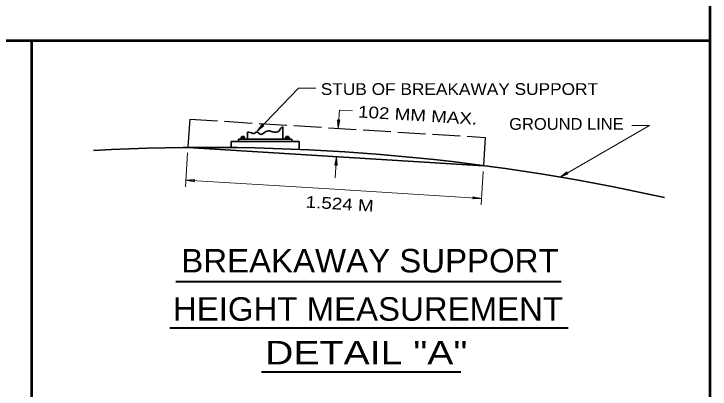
# Model space of a CAD drawing. Extents: x 312583 to 312854, y 144419 to 144597.
# Drawn here: x 312751.27 to 312796.35, y 144487.71 to 144511.98 of the extents above; entities that cross this region are included whole.
import ezdxf
from ezdxf.enums import TextEntityAlignment as Align

# ---------------------------------------------------------------- set-up
doc = ezdxf.new("R2010")
doc.units = 0
doc.header["$LTSCALE"] = 0.3
doc.linetypes.add('LONG_DASHED', pattern=[7.5, 6, -1.5])
doc.layers.add('1', color=7, linetype='Continuous', lineweight=13)

msp = doc.modelspace()

# ---------------------------------------------------------------- linework, layer by layer
at = {"layer": '1', "lineweight": 53}
for p, q in [((312796.3473, 144432.4767), (312796.3473, 144512.4926)), ((312796.3473, 144510.2401), (312717.1857, 144510.2401)), ((312752.4335, 144432.4767), (312752.4335, 144510.2401))]:
    msp.add_line(p, q, dxfattribs=at)
at = {"layer": '1'}
for p, q in [((312769.6944, 144507.1754), (312767.0264, 144504.4001)), ((312769.6944, 144507.1754), (312770.8137, 144507.1754)), ((312772.3471, 144505.7571), (312772.2781, 144504.5841)), ((312772.3471, 144505.7571), (312773.2057, 144505.7111)), ((312792.4153, 144504.7563), (312786.6377, 144501.4254)), ((312791.29, 144504.7563), (312792.4153, 144504.7563)), ((312762.3804, 144500.8044), (312762.5184, 144502.9894)), ((312772.0787, 144501.3871), (312772.1631, 144502.7364)), ((312781.5164, 144499.6238), (312781.6467, 144501.7858)), ((312762.4111, 144501.2338), (312771.6801, 144500.6588)), ((312781.5394, 144500.0531), (312771.6801, 144500.6588))]:
    msp.add_line(p, q, dxfattribs=at)
at = {"layer": '1', "linetype": 'LONG_DASHED', "lineweight": 25}
for p, q in [((312762.6564, 144505.1744), (312762.5414, 144503.3421)), ((312762.6564, 144505.1744), (312781.7847, 144503.9938)), ((312781.7847, 144503.9938), (312781.6697, 144502.1768))]:
    msp.add_line(p, q, dxfattribs=at)
at = {"layer": '1', "lineweight": 35}
for p, q in [((312768.6901, 144503.8864), (312768.6901, 144504.6761)), ((312766.3901, 144503.8864), (312766.3901, 144504.3311)), ((312765.3321, 144503.7254), (312765.3321, 144503.3804)), ((312765.8151, 144503.8864), (312765.8151, 144503.7254)), ((312765.8151, 144503.8864), (312769.2651, 144503.8864)), ((312765.9914, 144504.0091), (312765.9914, 144503.8864)), ((312766.0144, 144504.0244), (312766.1831, 144504.0244)), ((312766.0297, 144504.0628), (312766.0297, 144504.0244)), ((312766.0297, 144504.0628), (312766.1754, 144504.0628)), ((312766.0451, 144504.0091), (312766.0451, 144503.8864)), ((312766.1601, 144504.0091), (312766.1601, 144503.8864)), ((312766.1754, 144504.0628), (312766.1754, 144504.0244)), ((312766.2137, 144504.0091), (312766.2137, 144503.8864)), ((312768.8664, 144504.0091), (312768.8664, 144503.8864)), ((312768.8894, 144504.0244), (312769.0581, 144504.0244)), ((312768.9047, 144504.0628), (312768.9047, 144504.0244)), ((312768.9047, 144504.0628), (312769.0504, 144504.0628)), ((312768.9201, 144504.0091), (312768.9201, 144503.8864)), ((312769.0351, 144504.0091), (312769.0351, 144503.8864)), ((312769.0504, 144504.0628), (312769.0504, 144504.0244)), ((312769.0887, 144504.0091), (312769.0887, 144503.8864)), ((312769.2651, 144503.8864), (312769.2651, 144503.7254)), ((312762.5414, 144503.3344), (312781.6697, 144502.1538))]:
    msp.add_line(p, q, dxfattribs=at)
at = {"layer": '1', "lineweight": 40}
for p, q in [((312761.7556, 144494.6753), (312786.709, 144494.6753)), ((312761.3737, 144491.681), (312787.1546, 144491.681)), ((312767.2961, 144488.8355), (312780.2184, 144488.8355))]:
    msp.add_line(p, q, dxfattribs=at)
at = {"layer": '1'}
for points in [[(312772.3777, 144505.1284), (312772.2781, 144504.5841), (312772.2321, 144505.1361), (312772.3087, 144505.0748)], [(312767.4634, 144504.7528), (312767.0264, 144504.4001), (312767.3561, 144504.8524), (312767.3714, 144504.7604)], [(312772.0557, 144502.1921), (312772.1631, 144502.7364), (312772.2014, 144502.1844), (312772.1324, 144502.2381)], [(312787.1561, 144501.6433), (312786.6417, 144501.429), (312787.082, 144501.7746), (312787.0756, 144501.6778)], [(312762.9554, 144501.1264), (312762.4111, 144501.2338), (312762.9631, 144501.2721), (312762.9094, 144501.2031)], [(312780.9951, 144500.1528), (312781.5394, 144500.0531), (312780.9874, 144500.0148), (312781.0411, 144500.0838)]]:
    msp.add_lwpolyline(points, close=True, dxfattribs=at)
at = {"layer": '1', "lineweight": 35}
msp.add_lwpolyline([(312765.3321, 144503.7254), (312769.7404, 144503.7254), (312769.7404, 144503.2194)], dxfattribs=at)
for centre, radius, start, end in [((312766.0163, 144503.9942), 0.0311, 25.60064, 154.39936), ((312766.1005, 144503.9274), 0.0979, 55.04559, 124.95441), ((312766.1847, 144503.9942), 0.0311, 25.60064, 154.39936), ((312768.8913, 144503.9942), 0.0311, 25.60064, 154.39936), ((312768.9755, 144503.9274), 0.0979, 55.04559, 124.95441), ((312769.0597, 144503.9942), 0.0311, 25.60064, 154.39936), ((312763.8326, 144367.0421), 136.3071, 77.47167, 93.11775)]:
    msp.add_arc(centre, radius, start, end, dxfattribs=at)
msp.add_spline([(312766.3901, 144504.3311), (312766.5664, 144504.3158), (312766.7351, 144504.2544), (312766.8731, 144504.2698), (312766.9651, 144504.3388), (312767.0647, 144504.3234), (312767.2564, 144504.1931), (312767.4021, 144504.2468), (312767.7394, 144504.4154), (312768.0154, 144504.3541), (312768.4524, 144504.4154), (312768.5444, 144504.5688), (312768.6901, 144504.6761)], degree=3, dxfattribs=at)

# ---------------------------------------------------------------- texts
at = {"layer": '1'}
for s, width, p in [('STUB OF BREAKAWAY SUPPORT', 1.1, (312771.1434, 144506.7431)), ('GROUND LINE', 1.05, (312783.3415, 144504.4888))]:
    msp.add_text(s, height=0.76, dxfattribs=dict(at, width=width)).set_placement(p)
at = {"layer": '1', "width": 1.2}
for s, p in [('102 MM MAX.', (312773.5347, 144505.2898)), ('1.524 M', (312770.1437, 144499.4579))]:
    msp.add_text(s, height=0.76, rotation=356.473, dxfattribs=at).set_placement(p)
at = {"layer": '1'}
for s, width, p in [('BREAKAWAY SUPPORT', 1.05, (312774.3261, 144495.2589)), ('HEIGHT MEASUREMENT', 1.05, (312774.1988, 144492.1373)), ('DETAIL "A"', 1.25, (312774.0843, 144489.3093))]:
    msp.add_text(s, height=1.52, dxfattribs=dict(at, width=width)).set_placement(p, align=Align.CENTER)

doc.saveas('drawing.dxf')
